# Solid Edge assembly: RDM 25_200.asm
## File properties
Title: Zylinder
Author: ahadarics
Template: iso metric assembly.asm
Last saved by: ahadarics
Revision: 24
Application: Solid Edge
Username: ahadarics
Dokumentum tartalom típus: 1
Document Number: RDM 25/200
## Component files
Profilrohr.par
Kolbenstange.par
Kit_1.par
Kit_2.par
Mutter_1.par
Mutter_2.par
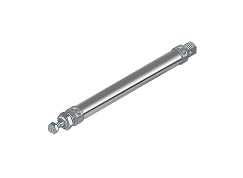
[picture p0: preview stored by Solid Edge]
